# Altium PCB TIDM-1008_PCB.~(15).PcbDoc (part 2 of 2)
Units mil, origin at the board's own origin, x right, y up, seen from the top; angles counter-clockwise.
Board outline 2200 x 2300 mil, 4 copper layers (Top Layer, Power Layer, Ground Plane, Bottom Layer), stack 79.834 mil thick; 196 components, 111 nets, 520 pads, 167 vias.
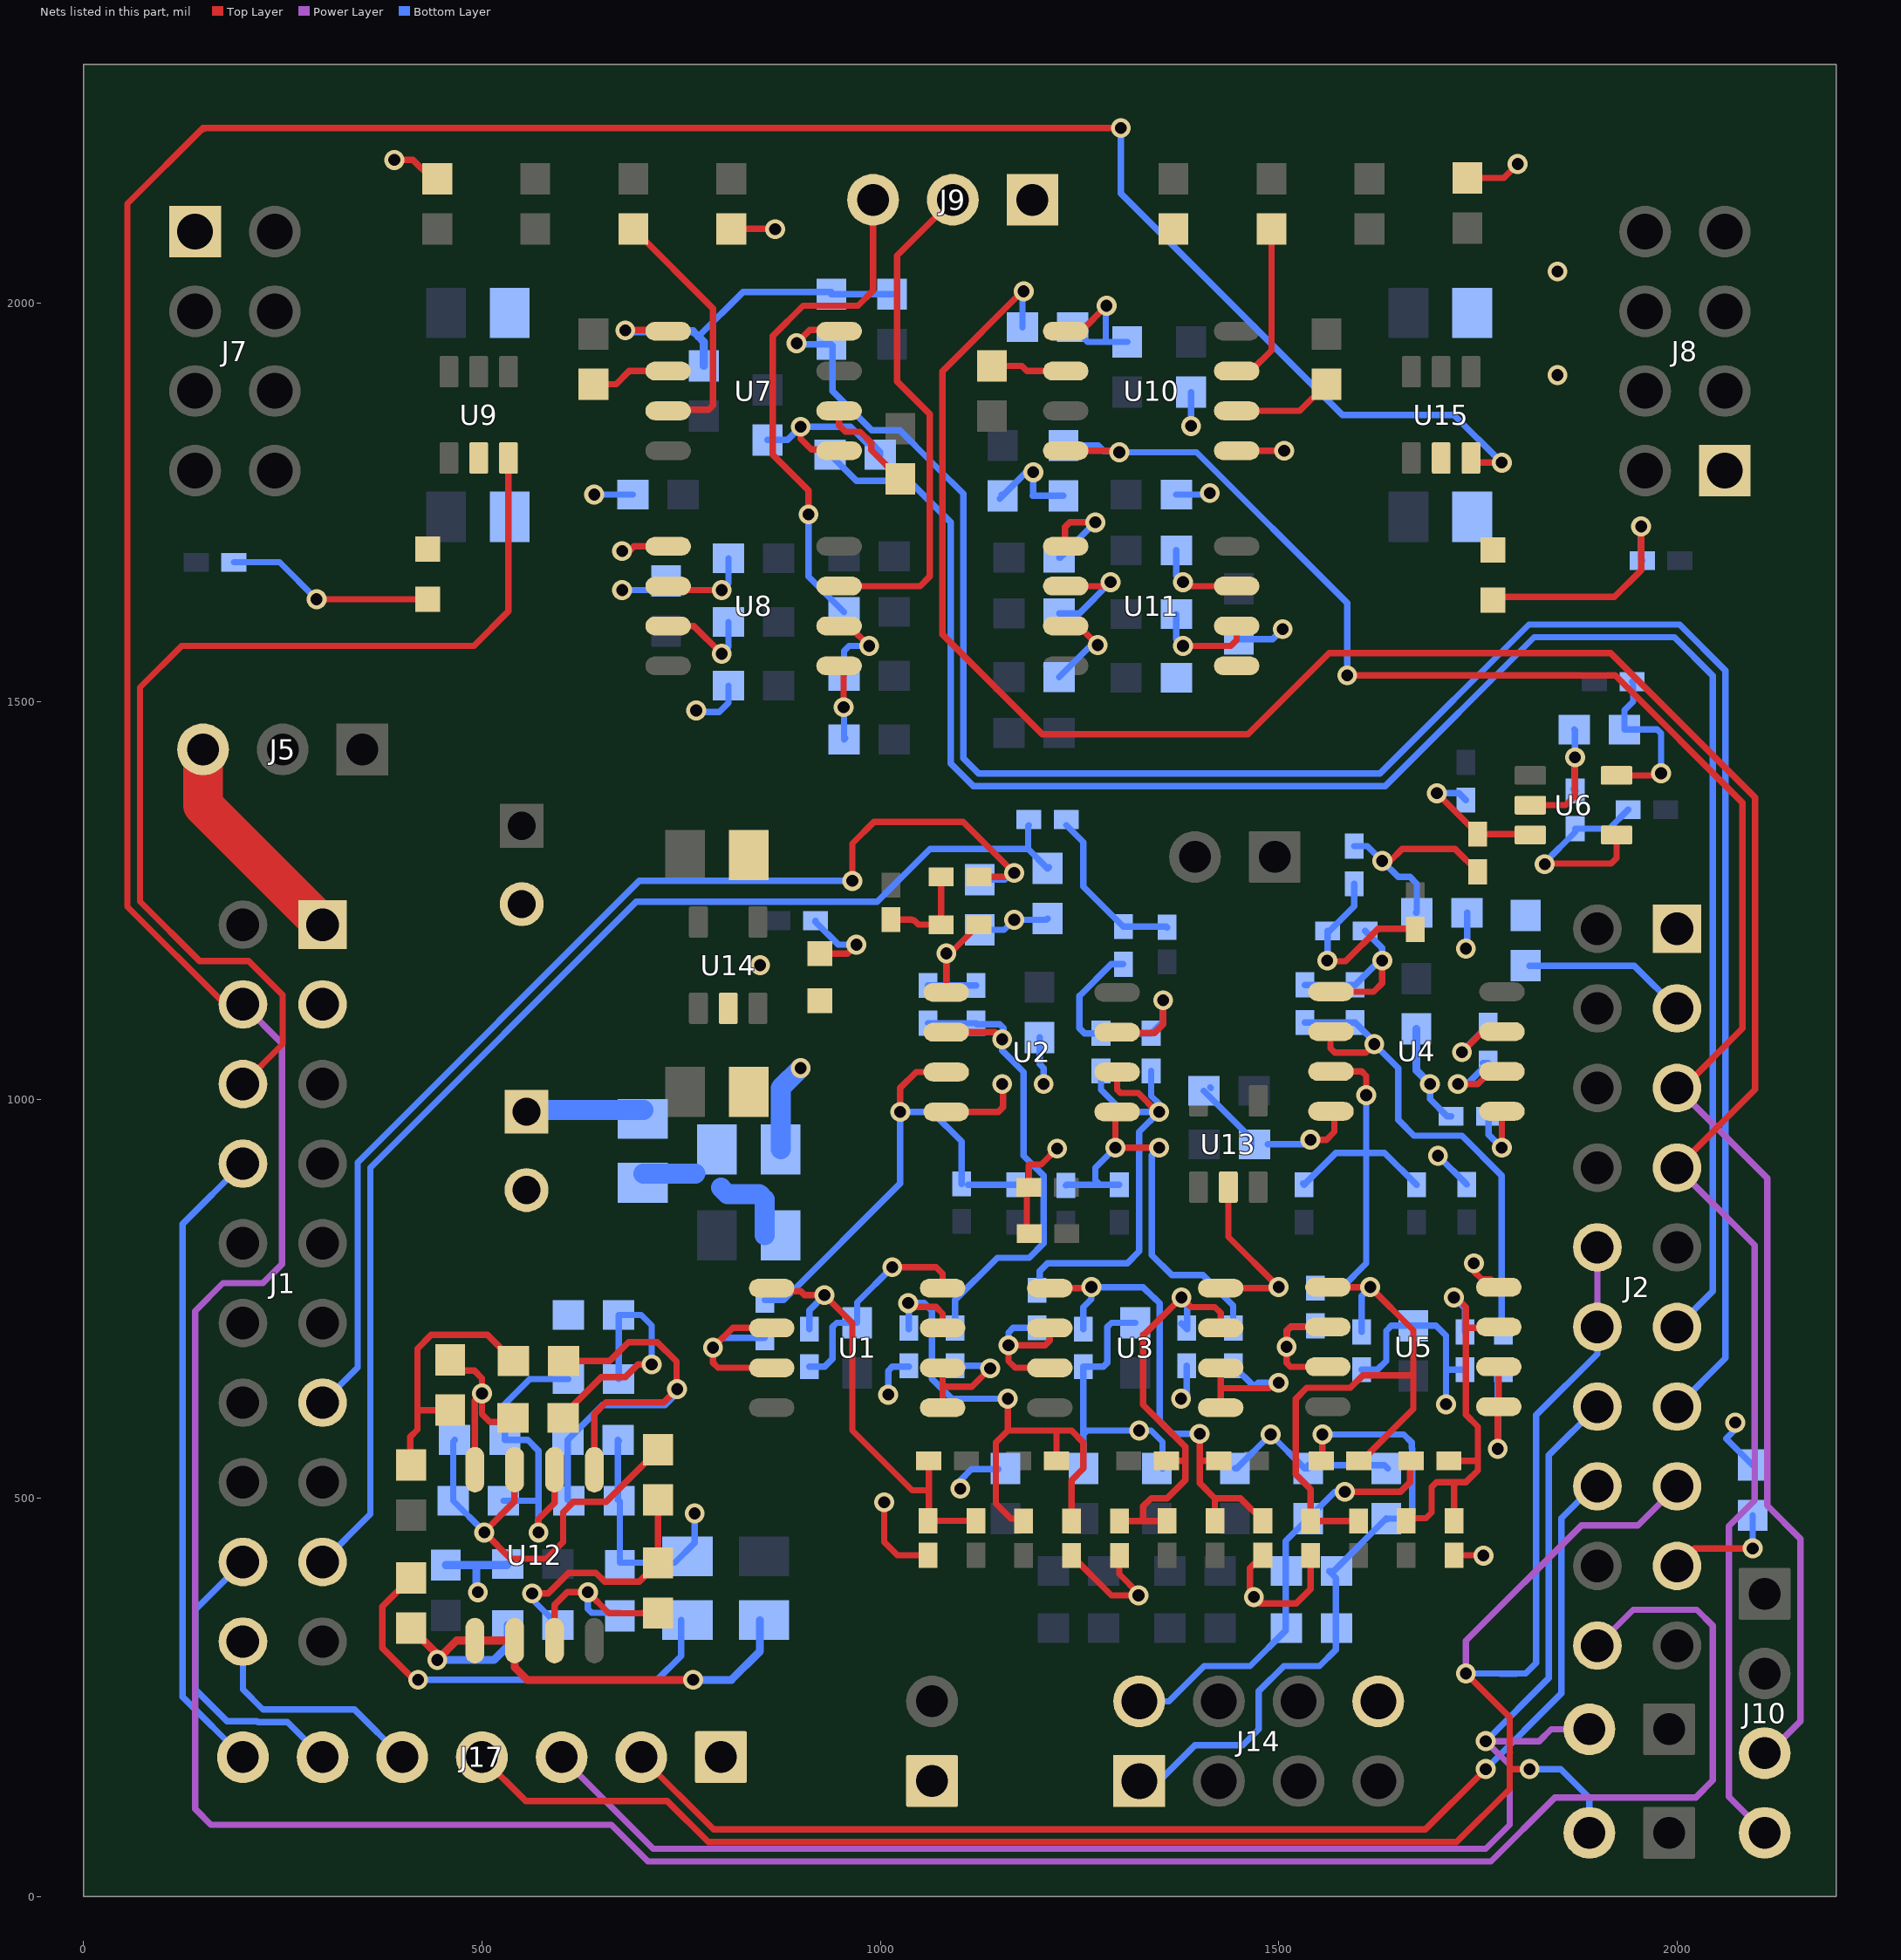
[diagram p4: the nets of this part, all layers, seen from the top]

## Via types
v1: diameter 25, hole 15, Top Layer to Bottom Layer, 167 vias

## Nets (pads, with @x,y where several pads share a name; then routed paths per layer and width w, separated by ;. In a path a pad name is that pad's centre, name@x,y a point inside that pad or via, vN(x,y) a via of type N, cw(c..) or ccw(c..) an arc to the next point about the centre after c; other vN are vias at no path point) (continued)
GND: C2.1 C3.1 C4.1 C5.2 C7.2 C8.2 C9.2 C10.2 C13.1 C14.1 C15.2 C17.2 C18.2 C19.2 C20.2 C23.1 C24.1 C25.1 C26.1 C27.2 C28.2 C30.2 C31.2 C32.2 C33.2 C35.1 C36.1 C37.2 C38.1 C39.1 C40.2 C41.1 C42.1 C43.2 C44.1 C45.1 C46.2 C49.2 C51.1 C52.2 C53.2 C54.1 C55.2 C56.1 C57.2 C58.1 C59.1 C60.2 C61.2 C62.2 C63.2 C64.2 C65.2 D2.2 D4.2 D7.2 D9.2 D12.2 D14.2 D16.1 D17.1 D18.2 J1.3 J2.1 J6.2 J7.1 J8.1 J9.1 J14.8 J15.1 J16.2 J17.1 R20.1 R40.2 R41.1 R56.2 R57.1 R64.1 R72.1 R73.1 R74.1 U1.4 U2.4 U3.4 U4.4 U5.4 U6.2 U7.5 U8.5 U9.2 U10.5 U11.5 U12.8 U13.2 U14.2 U15.2 | length 5177.7
  Top Layer w8: v1(390,2180) 413.5,2180 435.5,2158 C37.2@440,2162.5 ; C51.1@459.83,660.21 490.47,660.21 500.12,650.57 v1(500.12,631.57) ; U12.8@491.12,535.86 491.12,622.57 v1(500.12,631.57) ; C49.2@537.56,596 509.69,596 500.12,605.57 v1(500.12,631.57) ; v1(676,1689) 685,1689 691,1695 U8.5@733.72,1695 ; v1(680,1966) 686,1966 686.5,1966.5 U7.5@733.79,1966.5 ; C36.1@813,2093.5 v1@867.5,2093.5 ; v1(1005,495) 1005,445 1021.66,428.34 D4.2@1059.97,428.34 ; v1(1015,790) 1070,790 1078.25,781.75 U1.4@1078.25,763.73 ; U2.4@1082.72,985 1148,985 1154,991 1154,1019 v1(1153,1020) ; C10.2@1186.89,831.99 1184,834.88 1184,887.62 C20.2@1186.38,890 1186.38,918.38 1187,919 1202,919 v1(1222,939) ; D2.2@1240.03,428.03 1290.06,378 v1(1324,378) 1324,380.85 1300.09,404.76 D9.2@1300.09,428.04 ; U3.4@1427.28,763.73 1498.73,763.73 v1(1500,765) 1436.85,828.15 U13.2@1436.85,890.54 ; U10.5@1447.28,1815 v1(1507,1815) ; D7.2@1480.14,428.34 1464,412.19 1464,380 1468,376 v1(1469,376) 1469,375 1476,368 1522,368 1540,386 1540,427.88 D14.2@1540.16,428.04 ; v1(1540,950) 1560,950 1570,960 1570,981.45 U4.4@1565.69,985.76 ; D12.2@1720,428.16 D12.2@1720.2,428.36 1756.64,428.36 v1(1757,428) ; C43.2@1737,2157.5 1782.5,2157.5 v1(1800,2175) ; v1(1745,795) 1745,785 1755,775 1766.31,775 U5.4@1776.31,765 ; U6.2@1815.87,1370.01 1860.01,1370.01 1872,1382 v1(1872,1430) ; J2.1@2000,1201.5 J2.1@2000,1214.98
  Bottom Layer w8: C57.2@454.64,416.07 C57.2@455.15,416.57 ; v1(641,1760) C40.2@689.5,1760 ; R72.1@671.93,572 R72.1@670.79,573.14 670.79,498.29 C53.2@672.31,496.77 673.08,496 673.08,419.05 742.05,419.05 767,444 v1(767,481) ; v1(676,1640) 719.5,1640 C38.1@731,1651.5 ; v1(769,1489) 771,1487 798,1487 809.5,1498.5 C39.1@809.5,1520 ; 771.75,1958.25 827.88,2014.37 938.5,2014.37 R41.1@938.5,2011.5 R40.2@1014.87,2011.5 ; C9.2@910.97,665.11 930.11,665.11 940,675 940,715 945.22,720.22 C2.1@970.97,720.22 970.97,745.97 v1(1015,790) ; v1(1010,630) 1010,660 1015.11,665.11 C5.2@1035.97,665.11 ; v1(1100.36,512) 1100.36,522.36 1114.5,536.5 C3.1@1148,536.5 ; C7.2@1124.78,1213.5 1155.5,1213.5 v1(1168,1226) 1208.5,1226 C17.2@1210,1227.5 ; R56.2@1150,1754.87 R56.2@1153.63,1758.5 ; R56.2@1152.13,1760 R56.2@1153.63,1758.5 ; C4.1@1200,1078.5 1200,1045 1205,1040 v1(1205,1020) ; R57.1@1230,1758.5 1191.5,1758.5 1192,1759.01 v1(1192,1788) 1183.13,1788 R56.2@1153.63,1758.5 ; C8.2@1255,537.3 1255,580 ; C13.1@1320,720.22 1290.22,720.22 1285,715 1285,670 1280.11,665.11 C15.2@1255,665.11 1255,580 ; C18.2@1354.24,537.23 1354.24,570.76 1340,585 v1(1325,585) 1260,585 1255,580 ; C45.1@1371.5,1760 1411.71,1760 v1(1413.62,1761.91) v1@1417.15,1765.45 ; v1(1377.5,625) 1380,625 1385,630 1384.71,630.29 C19.2@1384.71,666.38 ; v1(1390,1846) C41.1@1390,1888.5 ; C58.1@1406,1011.54 1466,951.54 1466,940.11 C59.1@1465.89,940 ; C58.1@1414.2,1015.86 C58.1@1415,1015.06 ; C14.1@1445,537.5 1447.5,537.5 v1(1490,580) 1532.5,537.5 C25.1@1537,537.5 ; C44.1@1450,1578.5 1492.5,1578.5 v1(1505,1591) ; C59.1@1486.5,944.32 1534.32,944.32 v1(1540,950) ; v1@1507,1813 v1(1507,1815) ; C25.1@1537,541.5 1632.8,541.5 C31.2@1637,537.3 ; C32.2@1604.03,661.38 1623.93,661.38 1635,672.45 1635,710 1641.5,716.5 C23.1@1669.03,716.5 1697.5,716.5 1710,704 1710,663 ; v1(1690,1020) 1690,1001 1711.47,979.53 R20.1@1716.38,979.53 ; v1(1700,930) 1700,929.88 C33.2@1736,893.88 ; v1(1710,618) 1710,663 ; C28.2@1732.36,660 C28.2@1733.74,661.38 1711.62,661.38 1710,663 ; v1(1735,1190) 1736.5,1191.5 C30.2@1736.5,1235 ; C24.1@1871.07,1465 1872,1464.07 v1(1872,1430) 1872,1392.01 1870,1390.01 C27.2@1872.18,1387.82 C27.2@1872.36,1388 ; v1(2073,595) 2073,586.5 2061.5,575 R73.1@2095,541.5
  Bottom Layer w10: C57.2@454.64,416.07 492.9,416.07 ; v1(495,382) 492.9,384.1 492.9,416.07 ; C52.2@532.36,417.27 531.16,416.07 492.9,416.07 ; v1(680,1966) 681,1965 765,1965 771.75,1958.25 778.5,1951.5 C35.1@778.5,1921.5 ; C26.1@1672.97,1089.27 1672.97,1037.03 v1(1690,1020)
  Bottom Layer w25: C56.1@875,938 875,1015 v1(900,1040)
  other v1: 849.1,1169.14 1850,1910 1850,2040 868,2093
I+: C29.2 C31.1 J14.1 R26.1 R30.1 | length 822.3
  Top Layer w8: R30.1@1553.37,547.02 1555,548.66 1555,570 1560,575 v1(1555,580)
  Bottom Layer w8: J14.1@1325,145 1350,145 1395,190 1455,190 1475,210 1475,257.73 1506.63,289.35 1551.35,289.35 1572,310 1572,400.01 1563.47,408.54 1569.04,408.54 C31.1@1635,474.5 ; v1(1555,580) 1657,580 1667,570 1667,563.05 1667.57,562.47 1667.57,480.57 1661.3,474.3 1637,474.3 C31.1@1636.1,473.4
I-: C25.2 C29.1 J14.2 R24.1 R26.2 | length 547.4
  Top Layer w8: v1(1583,508) 1653,508 1665,520 1665,545.65 R24.1@1666.38,547.02
  Bottom Layer w8: J14.2@1325,245 1362.27,245 1406.63,289.35 1464.35,289.35 1509,334 1509,446.5 C25.2@1537,474.5 1570.5,508 v1(1583,508)
Launchpad-5V: J1.1 J5.3 | length 283.5
  Top Layer w50: J5.3@150,1440 150,1370 J1.1@300,1220
  Bottom Layer w25: J1.1@300,1220 J1.1@301,1219
NetC1_1: C1.1 R1.2 R5.1 U2.1 | length 205.1
  Top Layer w8: U2.1@1082.72,1135 1082.72,1183.72 v1(1083,1184) 1087.62,1184 R5.1@1123.62,1220
  Bottom Layer w8: C1.1@1060,1143.62 1082.72,1143.62 ; v1(1083,1184) 1083,1143.9 1082.72,1143.62 ; R1.2@1120,1143.62 1082.72,1143.62
NetC1_2: C1.2 R1.1 R3.2 U2.2 | length 640.8
  Top Layer w8: U2.2@1082,1084.28 U2.2@1082.72,1085 1144,1085 v1(1153,1076)
  Bottom Layer w8: C1.2@1060,1096.38 R1.1@1120,1096.38 1121.38,1095 1150,1095 1155,1090 1155,1078 v1(1153,1076) 1153,1062 1180,1035 1180,930 1205,905 1205,820 1186.89,801.89 1146.89,801.89 1093.98,748.98 R3.2@1093.98,713.62
NetC5_1: C5.1 D1.2 D2.1 R2.2 U1.3 | length 750.1
  Top Layer w8: v1(1035,745) 1039.96,740.04 1069.96,740.04 1078.25,731.75 U1.3@1078.25,713.73 ; v1(1160,625) 1160,585 ; D1.2@1180,471.34 1177.03,474.3 1164,474.3 1145,493.3 1145,570 1160,585 ; R2.2@1221.12,547.01 1221.12,584.88 1221,585 ; D2.1@1240.03,471.34 1240.03,522.33 1255,537.3 1255,570 1240,585 1221,585 ; 1160,585 1221,585
  Bottom Layer w8: v1(1035,745) v1@1035.97,745 ; C5.1@1035.97,712.35 v1@1035.97,745 ; v1(1160,625) 1090,625 1065,650 1065,735.04 1055.04,745 v1@1035.97,745
NetC9_1: C9.1 D4.1 D5.2 R7.2 U1.5 | length 570.8
  Top Layer w8: U1.5@862.41,765 U1.5@863.69,763.73 867.41,760 900,760 905,755 v1(930,755) 965,720 965,585 1040.03,509.97 1060.67,509.97 1060.87,509.77 ; R7.2@1059.97,546.11 R7.2@1060.87,547 1060.87,509.77 ; D5.2@1119.99,471.64 D4.1@1059.97,471.64 1060.87,472.54 1060.87,509.77
  Bottom Layer w8: C9.1@910.97,712.35 910.97,735.97 v1(930,755)
NetC11_2: C11.2 R8.2 R9.1 U2.3 | length 622.3
  Top Layer w8: v1(1025,985) 1025,1015 1045,1035 U2.3@1082.72,1035
  Bottom Layer w8: R8.2@855,748.62 878.62,748.62 1025,895 v1(1025,985) 1065,985 1102,948 C11.2@1102,894.62 ; C11.2@1110,893.62 R9.1@1170,893.62
NetC12_1: C12.1 R10.2 R14.1 U2.7 | length 345
  Top Layer w8: U2.7@1297.29,1085 1298.29,1084 1344,1084 1355,1095 v1(1355,1125)
  Bottom Layer w8: R14.1@1305,1170.38 1289.85,1170.38 1250.1,1130.63 1250,1130.63 1250,1090 1256.38,1083.62 R10.2@1277.03,1083.62 C12.1@1340,1083.62 1355,1098.62 v1(1355,1125)
NetC12_2: C12.2 R10.1 R12.2 U2.6 | length 595.8
  Top Layer w8: U2.6@1297.29,1035 1297.29,1012.71 1301.32,1008.68 1323.83,1008.68 1347.51,985 v1(1350,985)
  Bottom Layer w8: R12.2@1196.99,761.08 1200,764.09 1200,785 1210,795 1310,795 1325,810 1325,960 v1(1350,985) ; R10.1@1277.03,1036.38 1277.03,1012.97 1305,985 v1(1350,985) ; C12.2@1340,1036.38 1340,1005 1350,995 v1(1350,985)
NetC15_1: C15.1 D6.2 D7.1 R11.2 U3.5 | length 622.3
  Top Layer w8: U3.5@1212.72,763.73 1263.73,763.73 v1(1265,765) ; v1(1400.87,580.87) 1400.87,545 ; D6.2@1420.11,471.65 1420,471.76 1420,500 ; R11.2@1424.9,547.01 1402.88,547.01 1400.87,545 ; D7.1@1480.14,471.65 1451.79,500 1420,500 ; 1400.87,545 1400.87,519.13 1420,500
  Bottom Layer w8: C15.1@1255,712.35 1255,740 1265,750 v1(1265,765) 1330,765 1343.22,751.78 1343.62,751.78 1350.57,744.83 1350.57,596.87 1366.58,580.87 v1(1400.87,580.87)
NetC19_1: C19.1 D9.1 D10.2 R16.2 U3.3 | length 569.4
  Top Layer w8: D9.1@1300.09,471.35 1330,471.35 ; R16.2@1359.13,547.01 1382.99,547.01 ; D10.2@1360.1,471.65 1359.79,471.35 1330,471.35 ; U3.3@1427.28,713.73 1427.28,732.72 1420,740 1390,740 v1(1378,752) 1331,705 1330,705 1330,617.28 1382.99,564.29 1382.99,547.01 ; 1330,471.35 1330,490 1340,500 1360,500 1382.99,522.99 1382.99,547.01
  Bottom Layer w8: C19.1@1378,719.35 1385,712.35 1385,745 v1(1378,752)
NetC21_2: C21.2 R18.2 R19.1 U2.5 | length 544.5
  Top Layer w8: U2.5@1297.29,985 1295,982.71 v1(1295,940) v1(1350,940)
  Bottom Layer w8: R19.1@1232.97,892.62 1233.97,893.62 1276,893.62 ; v1(1295,940) 1270,915 1270,899.62 1276,893.62 ; v1(1350,940) 1340.87,930.87 1340.87,805 1365.87,780 1405,780 1443.01,741.99 R18.2@1443.01,716.08 ; 1276,893.62 C21.2@1300,893.62 1276,893.62
NetC22_1: C22.1 R22.2 R27.1 U4.1 | length 252.8
  Top Layer w8: U4.1@1565.69,1135.76 1619.24,1135.76 1630,1146.52 v1(1630,1175)
  Bottom Layer w8: C22.1@1532.97,1144.38 R22.2@1595.94,1144.38 1626.56,1175 v1(1630,1175) 1630,1190.65 R27.1@1608.66,1211.99
NetC22_2: C22.2 R22.1 R25.2 U4.2 | length 633.8
  Top Layer w8: U4.2@1565.69,1085.76 1565,1085.07 1565,1065 1570.55,1059.45 1609.45,1059.45 v1(1620,1070)
  Bottom Layer w8: C22.2@1532.97,1097.14 R22.1@1595.94,1097.14 1620,1073.08 v1(1620,1070) 1650,1040 1650,975 1670,955 1730,955 1780,905 R25.2@1780,720.37
NetC24_2: C24.2 R21.1 U6.5 | length 216.4
  Top Layer w8: U6.5@1924.13,1407.41 v1@1977.41,1407.41
  Bottom Layer w8: R21.1@1943.62,1525 1945,1523.62 1945,1500 1934.07,1489.07 C24.2@1934.07,1465 1975,1465 1980,1460 v1(1980,1410)
NetC27_1: C27.1 R23.2 U6.4 | length 258.9
  Top Layer w8: v1(1834,1296) 1834.75,1296.75 1917.3,1296.75 1924.13,1303.58 U6.4@1924.13,1332.6
  Bottom Layer w8: v1(1834,1296) 1834,1298 1872.18,1336.18 C27.1@1872.18,1340.58 1914.94,1340.58 R23.2@1938.56,1364.2
NetC28_1: C28.1 D11.2 D12.1 R24.2 U5.3 | length 543.1
  Top Layer w8: D11.2@1660.19,471.65 1663.53,475 1685,475 1692,482 1692,514 1698,520 1720,520 ; R24.2@1713.62,547.02 1747.02,547.02 1750,550 ; v1(1720,752) 1723,752 1735,740 1735,714 ; D12.1@1720.2,471.67 1720.2,519.8 1720,520 ; U5.3@1776.31,715 1775.31,714 1735,714 ; 1720,520 1735,520 1750,535 1750,550 ; 1735,714 1735,605 1750,590 1750,550
  Bottom Layer w8: v1(1720,752) 1733.26,738.74 1733.74,738.74 C28.1@1733.74,708.62
NetC30_1: C30.1 R28.2 R29.1 | length 273.6
  Top Layer w8: v1(1630,1300) 1640,1300 1655,1315 1721.38,1315 R29.1@1750,1286.38
  Bottom Layer w8: R28.2@1595,1318.62 1611.38,1318.62 v1(1630,1300) 1650,1280 1665,1280 1673.5,1271.5 C30.1@1673.5,1235 C30.1@1672.53,1235
NetC32_1: C32.1 D14.1 D15.2 R30.2 U5.5 | length 766.5
  Top Layer w8: U5.5@1561.75,765 v1(1615,765) 1669.03,710.97 1669.03,653.5 ; D15.2@1600.18,471.34 D14.1@1540.16,471.34 1540.16,511.17 1521.33,530 1521.33,624.81 1535.2,638.68 1589.94,638.68 1605.63,654.37 1668.16,654.37 1669.03,653.5 ; R30.2@1600.61,547.02 1604.02,547.02 1669,612 1669,634 ; 1669.03,634.03 1669.03,653.5
  Bottom Layer w8: C32.1@1604.03,708.62 1604.03,754.03 v1(1615,765)
NetC34_2: C34.2 R32.2 R33.1 U4.3 | length 534.9
  Top Layer w8: U4.3@1565.69,1035.76 1604.24,1035.76 1610,1030 v1(1610,1006)
  Bottom Layer w8: C34.2@1530.5,895 C34.2@1531.88,893.62 1571.88,933.62 1610,933.62 ; R32.2@1546.02,763.62 1547.4,765 1580,765 1610,795 1610,933.62 ; v1(1610,1006) 1610,933.62 ; R33.1@1672.97,893.62 1632.97,933.62 1610,933.62
NetC47_1: C47.1 R66.2 R67.1 U12.7 | length 538.8
  Top Layer w8: U12.7@541.66,535.31 U12.7@541.12,535.86 541,535.74 541,496 503,458 v1(503,457) 536,424 581,424 602,445 602,482.46 614.98,495.44 655.76,495.44 R67.1@721.08,560.76
  Bottom Layer w8: R66.2@465.86,573.14 464.07,571.35 C47.1@464.07,496.77 503,457.85 v1(503,457)
NetC47_2: C47.2 R65.2 R66.1 U12.6 | length 417.3
  Top Layer w8: v1(571,457) 571,473.91 591.12,494.02 U12.6@591.12,535.86
  Bottom Layer w8: C47.2@527.06,496.77 568.92,496.77 ; v1(571,457) 571,559.69 557.55,573.14 R66.1@528.85,573.14 528.85,618.31 560.12,649.58 R65.2@608.62,649.58
NetC48_1: C48.1 C50.2 R71.2 U12.1 U12.2 | length 691.4
  Top Layer w10: R71.2@411.09,337.04 444,304.13 v1(444,297) 468.29,321.29 U12.1@491.12,321.29 U12.2@541.12,321.29 541.12,287.88 557,272 v1(765,272)
  Bottom Layer w10: v1@440,302 444,298 v1(444,297) 515,297 532.36,314.36 C48.1@532.36,340.9 ; v1(765,272) 813,272 849,308 C50.2@849,347
NetC48_2: C48.2 R67.2 R68.1 | length 316.7
  Top Layer w8: v1(563.12,380.57) 583.12,380.57 608.92,406.37 643.1,406.37 654.33,395.14 697.39,395.14 R68.1@721.08,418.82 R67.2@721.08,497.77
  Bottom Layer w8: v1@563.92,379.77 v1(563.12,380.57) 563.12,373.14 C48.2@595.36,340.9 C48.2@595.03,340.57
NetC49_1: C49.1 R64.2 R65.1 | length 317.1
  Top Layer w8: C49.1@601.75,600.96 601.75,603.75 650,652 680,652 696,668 v1(713,668)
  Bottom Layer w8: R65.1@671.5,649.7 R65.1@671.61,649.58 671.61,729.88 R64.2@671.5,730 699.95,730 713,716.95 v1(713,668)
NetC51_2: C51.2 R69.2 R70.1 | length 333.7
  Top Layer w8: R69.2@411.15,541.97 410,543.12 410,577 419.12,586.12 419.12,612 ; C51.2@459.18,596.57 C51.2@459.83,597.22 ; C51.2@460,610.5 420.61,610.5 419.12,612 ; R70.1@539.62,672.37 507,704.99 507,705.06 436.38,705.06 419.12,687.79 419.12,612
NetC53_1: C53.1 R70.2 R72.2 U12.5 | length 628.9
  Top Layer w8: R70.2@604.15,673.91 R70.2@602.61,672.37 660.37,672.37 684,696 720,696 744.37,671.63 744.37,637.63 v1(745,637) 728.13,620.13 655.67,620.13 641.12,605.57 U12.5@641.12,535.86
  Bottom Layer w8: C53.1@609.31,496.77 607.8,498.29 R72.2@607.8,573.14 651.65,617 730,617 745,632 v1(745,637)
NetC54_2: C54.2 R68.2 U12.3 | length 235.5
  Top Layer w8: U12.3@591.12,321.29 591.12,366.12 607,382 v1(633,382) 659.43,355.57 700.82,355.57 701.08,355.83
  Bottom Layer w8: v1(633,382) 633,361 637.94,356.06 C54.2@673.08,356.06
NetC55_1: C55.1 R71.1 | length 552
  Top Layer w8: R71.1@411.09,400.03 375,363.94 375,312 415,272 v1(420,272)
  Bottom Layer w8: v1(420,272) 720,272 750,302 C55.1@750,347
NetC56_2: C56.2 L1.2 L2.1 | length 176.6
  Bottom Layer w25: L1.2@702.57,907.32 767.68,907.32 ; 800,890 808.13,881.87 848.13,881.87 855,875 855,830 L2.1@855,835.31
NetD3_2: D3.2 R5.2 R6.1 | length 125.5
  Top Layer w8: D3.2@1013.49,1226.35 1039.18,1226.35 1039.9,1225.63 1042.37,1225.63 1048,1220 R5.2@1076.38,1220 R6.1@1076.38,1280
NetD8_2: D8.2 R14.2 R15.1 | length 212.3
  Bottom Layer w8: R15.1@1233.62,1345 1255,1323.62 1255,1267.62 R14.2@1305,1217.62 1359.03,1217.62 D8.2@1360,1216.65
NetD13_2: D13.2 R27.2 R28.1 | length 240.8
  Top Layer w8: v1@1561,1174 1584,1174 1625,1215 1670.62,1215 D13.2@1671.51,1214.11
  Bottom Layer w8: v1@1561,1174 1561,1181 1561.41,1181.41 R27.2@1561.41,1211.99 1563.99,1211.99 1595,1243 R28.1@1595,1271.38
  other v1: 1561,1175
NetD16_2: D16.2 R48.1 | length 262.6
  Top Layer w8: v1(292.5,1628.5) D16.2@432,1628.5
  Bottom Layer w8: R48.1@188.62,1675 246,1675 v1(292.5,1628.5)
NetD17_2: D17.2 R54.1 | length 299.6
  Top Layer w8: D17.2@1768.02,1631.47 1921.47,1631.47 1955,1665 v1(1955,1720)
  Bottom Layer w8: v1(1955,1720) 1955,1678.22 R54.1@1956.38,1676.84
NetD18_1: D18.1 R78.1 | length 117.2
  Top Layer w8: D18.1@925.43,1185 D18.1@924.1,1183.66 958.66,1183.66 v1(970,1195)
  Bottom Layer w8: R78.1@918.62,1225 918.62,1223.38 947,1195 v1(970,1195)
NetJ9_2: J9.2 U8.3 | length 646.1
  Top Layer w8: U8.3@948.28,1645 1050,1645 1062.13,1657.13 1062.13,1861 1021,1902.13 1021,2060 J9.2@1091,2130 ; J9.2@1074.13,2124.13 J9.2@1080,2130
NetJ9_3: J9.3 R45.1 | length 647.2
  Top Layer w8: v1(910,1735) 910,1765 865,1810 865,1959 903,1997 972,1997 991,2016 J9.3@991,2130
  Bottom Layer w8: v1(910,1735) 910,1657 R45.1@954.5,1612.5
NetJ16_1: J16.1 L1.1 | length 147.4
  Bottom Layer w25: J16.1@556,985.21 558.1,987.32 L1.1@702.57,987.32
NetR3_1: R3.1 U1.1 U1.2 | length 166.6
  Top Layer w8: U1.1@1078.25,613.73 1078.25,640 ; U1.2@1078.25,663.73 1078.25,640 ; v1(1138,663) 1115,640 1078.25,640
  Bottom Layer w8: R3.1@1095.36,665 R3.1@1093.98,666.38 1134.62,666.38 v1(1138,663)
NetR8_1: R8.1 U1.6 U1.7 | length 251.4
  Top Layer w8: U1.7@862.41,665 U1.7@863.69,663.73 796.27,663.73 790,670 v1(790,689) 815,714 863.41,714 U1.6@863.69,713.73
  Bottom Layer w8: v1(790,689) 802.38,701.38 R8.1@855,701.38
NetR12_1: R12.1 U3.6 U3.7 | length 212
  Top Layer w8: U3.6@1212,713.01 U3.6@1212.72,713.73 1212.72,697.72 1207,692 v1(1161,692) 1161,672 1169.27,663.73 U3.7@1212.72,663.73
  Bottom Layer w8: v1@1169,694 1164,689 v1(1161,692) 1161,708 1166.83,713.83 R12.1@1196.99,713.83
NetR17_1: R17.1 U4.7 | length 108.2
  Top Layer w8: v1(1730,1060) 1755.76,1085.76 U4.7@1780.25,1085.76
  Bottom Layer w8: v1(1730,1060) 1730,1060.65 R17.1@1762.97,1093.62
NetR17_2: R17.2 U4.6 | length 117.3
  Top Layer w8: v1(1725,1020) 1750,1020 1765.76,1035.76 U4.6@1780.25,1035.76
  Bottom Layer w8: v1(1725,1020) 1736.59,1020 R17.2@1762.97,1046.38 R17.2@1756.38,1046.38
NetR18_1: R18.1 U3.1 U3.2 | length 195.6
  Top Layer w8: U3.1@1427.28,613.73 1427.28,638.09 ; U3.2@1427.28,663.73 1427.28,638.09 ; v1(1500,645) 1495,645 1488.09,638.09 1427.28,638.09
  Bottom Layer w8: R18.1@1443.01,666.38 1469.39,640 1474.39,645 v1(1500,645)
NetR20_2: R20.2 U4.5 | length 82.2
  Top Layer w8: v1@1780,950 1780.25,950.25 U4.5@1780.25,985.76
  Bottom Layer w8: R20.2@1763.62,979.53 1763.62,956.38 v1(1780,940)
NetR25_1: R25.1 U5.1 U5.2 | length 205.8
  Top Layer w8: v1(1775,562) 1775,613.69 U5.1@1776.31,615 U5.2@1776.31,665
  Bottom Layer w8: v1(1775,562) 1775,654.38 R25.1@1782,661.38
NetR29_2: R29.2 R31.1 U6.3 | length 178.9
  Top Layer w8: v1(1698.62,1385) R29.2@1750,1333.62 1814.85,1333.62 U6.3@1815.87,1332.6
  Bottom Layer w8: v1(1698.62,1385) 1726.38,1385 R31.1@1735,1376.38
NetR32_1: R32.1 U5.6 U5.7 | length 206.3
  Top Layer w8: U5.7@1561.75,665 1515,665 1510,670 v1(1510,690) 1510,710 1515,715 U5.6@1561.75,715
  Bottom Layer w8: v1(1510,690) 1510,710 1515,715 1544.64,715 R32.1@1546.02,716.38
NetR34_1: R34.1 U7.7 | length 321.4
  Top Layer w8: R34.1@690,2093.5 790,1993.5 790,1872 784.5,1866.5 U7.7@733.79,1866.5
NetR35_1: R35.1 R36.2 U7.1 | length 233.9
  Top Layer w8: v1(900,1845) 900,1830 913.5,1816.5 U7.1@948.36,1816.5
  Bottom Layer w8: R35.1@858.5,1828.5 883.5,1828.5 v1(900,1845) 962.55,1845 982.85,1824.7 988.85,1824.7 1000,1813.55 R36.2@1000,1810
NetR37_1: R37.1 U7.2 | length 129.5
  Top Layer w8: U7.2@948.36,1866.5 948.36,1846.82 956.5,1838.68 974.83,1838.68 988.7,1824.81 988.7,1815.8 R37.1@1025,1779.5
NetR39_1: R39.1 U7.6 | length 105.5
  Top Layer w8: R39.1@640,1898.5 668.5,1898.5 685,1915 U7.6@733.72,1915 U7.6@730.21,1918.5
NetR42_1: R42.1 U8.7 | length 125.3
  Top Layer w8: U8.7@733.72,1595 766,1595 v1(801,1560)
  Bottom Layer w8: v1(801,1560) 809.5,1568.5 R42.1@809.5,1600
NetR43_1: R43.1 U8.1 | length 109.6
  Top Layer w8: U8.1@951,1542.28 U8.1@948.28,1545 950,1543.28 954,1539.28 v1(954,1493) v1@954,1499.43
  Bottom Layer w8: v1(954,1493) 954,1486 954.5,1485.5 R43.1@954.5,1455.49 ; R43.1@954.5,1455.49 R43.1@954.5,1452.5 956,1454 R43.1@954.5,1455.49
NetR44_1: R44.1 U8.2 | length 113.3
  Top Layer w8: U8.2@948.28,1595 961,1595 v1(986,1570)
  Bottom Layer w8: R44.1@954.5,1532.5 954.5,1563.5 961,1570 v1(986,1570)
NetR47_1: R47.1 U8.6 | length 112.9
  Top Layer w8: U8.6@733.72,1645 738.72,1640 v1(801,1640)
  Bottom Layer w8: v1(801,1640) 809.5,1648.5 R47.1@809.5,1680
NetR49_1: R49.1 U10.7 | length 207
  Top Layer w8: U10.7@1447.28,1915 1465,1915 1491,1941 R49.1@1491,2093.5
NetR50_1: R50.1 R51.2 U10.1 | length 186.6
  Top Layer w8: U10.1@1232.72,1965 1252,1965 v1(1284,1997)
  Bottom Layer w8: R51.2@1241.5,1970 1260,1951.5 1283,1951.5 ; v1(1284,1997) 1284,1987 1283,1986 1283,1951.5 ; R50.1@1310,1951.5 1283,1951.5
NetR52_1: R52.1 U10.2 | length 104.6
  Top Layer w8: R52.1@1140,1921.5 1177.5,1921.5 1184,1915 U10.2@1232.72,1915 U10.2@1226.22,1921.5
NetR55_1: R55.1 U10.6 | length 126.6
  Top Layer w8: U10.6@1447.28,1865 1526.5,1865 R55.1@1560,1898.5
NetR58_1: R58.1 U11.7 | length 112.9
  Top Layer w8: v1(1380,1650) 1385,1645 U11.7@1447.28,1645
  Bottom Layer w8: R58.1@1371.5,1690 1371.5,1658.5 v1(1380,1650)
NetR59_1: R59.1 U11.1 | length 135.9
  Top Layer w8: U11.1@1240,1695 U11.1@1232.72,1695 1232,1695.72 1232,1719 1238,1725 v1(1270,1725)
  Bottom Layer w8: R59.1@1224.5,1680.78 1225.78,1680.78 v1(1270,1725)
NetR60_1: R60.1 U11.2 | length 139.1
  Top Layer w8: U11.2@1232.72,1645 1284,1645 v1(1289,1650)
  Bottom Layer w8: R60.1@1224.5,1610.78 1249.78,1610.78 v1(1289,1650)
NetR61_1: R61.1 U11.3 | length 115.4
  Top Layer w8: U11.3@1232.72,1595 1249,1595 v1(1273,1571)
  Bottom Layer w8: R61.1@1224.5,1530.78 1264.71,1571 v1(1273,1571)
NetR63_1: R63.1 U11.6 | length 131.5
  Top Layer w8: v1(1380,1570) 1440,1570 1447.28,1577.28 U11.6@1447.28,1595
  Bottom Layer w8: R63.1@1371.5,1610 1371.5,1578.5 v1(1380,1570)
PTO-IN-1: J1.8 J17.7 | length 807.9
  Bottom Layer w8: J17.7@200,175 124.13,250.87 124.13,844.13 J1.8@200,920
PTO-IN-2: J1.18 J17.6 | length 380.1
  Bottom Layer w8: J1.18@200,420 140,360 140,260 180,220 217.55,220 218.2,219.35 218.37,219.35 218.6,219.13 255.87,219.13 J17.6@300,175
PTO-IN-3: J1.20 J17.5 | length 295.2
  Bottom Layer w8: J1.20@200,320 200,260 224.77,235.23 224.95,235.23 225.18,235 340,235 J17.5@400,175
PTO-OUT-1: J2.10 J2.12 J2.15 J11.2 J17.4 | length 2722.8
  Top Layer w8: J17.4@500,175 555,120 732.55,120 784.3,68.25 1723.25,68.25 1790,135 1790,160 ; v1(1735,280) 1790,225 1790,201.47 ; 1790,181.28 1790,201.47 ; 1790.37,180.9 1790,180.53 1790,160 ; 1790.37,201.1 1790,201.47 ; v1(1815,160) 1790,160
  Power Layer w8: v1(1735,280) 1735,321 1880,466 1951.02,466 J2.15@2000,514.98 ; J2.12@1900,714.98 J2.10@1900,814.98
  Bottom Layer w8: v1(1735,280) 1777.53,280 1777.9,279.63 1798.1,279.63 1798.47,280 1810,280 1823.25,293.25 1823.25,604.25 1900,681 J2.12@1900,714.98 ; v1(1815,160) 1854,160 1890,124 J11.2@1890,80
PTO-OUT-2: J2.14 J12.2 J17.3 | length 1981.7
  Power Layer w8: J17.3@600,175 715,60 1760,60 1790,90 1790,165 v1(1760,195) 1827,195 1842,210 J12.2@1890,210
  Bottom Layer w8: v1(1760,195) 1839.13,274.13 1839.13,554.11 J2.14@1900,614.98
PTO-OUT-3: J2.16 J17.2 | length 1542.2
  Top Layer w8: J17.2@700,175 790.87,84.13 1684.13,84.13 1754.5,154.5 v1@1764.5,154.5
  Bottom Layer w8: v1(1760,160) 1855,255 1855,475 J2.16@1894.98,514.98
PWREN1: J1.6 U9.3 | length 1323.5
  Top Layer w8: J1.6@200,1020 250,1070 250,1131.69 207.2,1174.49 145.51,1174.49 70.87,1249.13 70.87,1517.87 123,1570 490,1570 533.4,1613.4 U9.3@533.4,1805.87
PWREN2: J1.4 J2.20 U15.3 | length 6551.6
  Top Layer w8: J1.4@200,1120 177.55,1120 55,1242.55 55,2125 150,2220 151,2219 152,2220 v1(1302,2220) ; U15.3@1741.4,1805.87 1747.27,1800 v1(1780,1800)
  Power Layer w8: J1.4@200,1120 249,1071 249,794 225,770 175,770 140,735 140,110 160,90 662.55,90 708.42,44.13 1766.58,44.13 1846.8,124.35 2023.48,124.35 2045,145.87 2045,340 2025,360 1945.02,360 J2.20@1900,314.98
  Bottom Layer w8: v1(1302,2220) 1302,2138.02 1580.02,1860 1720,1860 v1(1780,1800)
SinCos-A: C7.1 J1.13 R6.2 | length 1473
  Top Layer w8: v1@965,1270 965,1322 992,1349 1104,1349 v1(1168,1285) 1165,1285 1160,1280 R6.2@1123.62,1280
  Bottom Layer w8: J1.13@300,620 344.13,664.13 344.13,921.58 697.55,1275 v1(965,1275) ; C7.1@1124.78,1276.49 1156.49,1276.49 1165,1285 v1(1168,1285)
SinCos-B: C17.1 J1.17 R15.2 | length 1578.2
  Bottom Layer w8: J1.17@300,420 360,480 360,915 693.78,1248.78 996.22,1248.78 1062.45,1315 1185.5,1315 ; R15.2@1186.38,1345 1185.5,1344.12 1185.5,1315 ; C17.1@1211.5,1292 C17.1@1210,1290.5 1185.5,1315
SPI-1-SIMO: J2.11 R36.1 | length 2395.6
  Top Layer w8: J2.11@2000,714.98 J2.11@2002.98,712
  Bottom Layer w8: R36.1@937.01,1810 970,1777.01 1036.54,1777.01 1088.25,1725.3 1088.25,1422.48 1116.85,1393.88 1633.78,1393.88 1820.77,1580.87 1996.58,1580.87 2045,1532.45 2045,759.98 J2.11@2000,714.98
SPI-1-SOMI: J2.13 R41.2 U7.4 | length 2728.4
  Top Layer w8: v1(895,1950) 911.5,1966.5 U7.4@948.36,1966.5
  Bottom Layer w8: v1(895,1950) 896.5,1948.5 R41.2@938.5,1948.5 940,1947.01 940,1890 989.43,1840.57 1024.6,1840.57 1065.75,1799.43 1065.75,1799.33 1089.33,1775.75 1089.43,1775.75 1104.13,1761.05 1104.13,1429.05 1123.42,1409.75 1627.2,1409.75 1814.2,1596.75 2003.15,1596.75 2060.87,1539.02 2060.87,675.86 J2.13@2000,614.98
SPI-2-SIMO: J2.7 J10.4 R51.1 | length 3117.7
  Top Layer w8: v1@1178.33,2015 1078,1914.67 1078,1584.55 1203.42,1459.13 1461.58,1459.13 1563.45,1561 1916.9,1561 2098.13,1379.77 2098.13,1013.11 J2.7@2000,914.98
  Power Layer w8: J2.7@2000,914.98 2097.37,817.61 2097.37,497.37 2065,465 2065,125 J10.4@2110,80
  Bottom Layer w8: R51.1@1178.5,1970 v1@1178.5,2013.5
  other v1: 1180,2015
SPI-2-SOMI: J2.5 J10.3 R57.2 U10.4 | length 2496.9
  Top Layer w8: U10.4@1232.72,1815 1298,1815 v1(1300,1813) ; v1(1586,1533) 1922.45,1533 2082.25,1373.2 2082.25,1089.68 2007.56,1014.98 J2.5@2000,1014.98
  Power Layer w8: J2.5@2000,1014.98 2113.25,901.74 2113.25,490.8 2155,449.05 2155,220 2110,175 J10.3@2110,193
  Bottom Layer w8: R57.2@1230,1821.5 1273.5,1821.5 1280,1815 1298,1815 v1(1300,1813) 1397,1813 1586,1624 v1(1586,1533)
"SPISTEA / SPISTEB": J2.3 R74.2 | length 207.2
  Bottom Layer w8: R74.2@1815,1168.5 1946.48,1168.5 J2.3@2000,1114.98
SPISTEC: J2.17 R73.2 | length 160.6
  Top Layer w8: J2.17@2000,414.98 2022.02,437 v1(2095,437)
  Bottom Layer w8: J2.17@2000,400 J2.17@2000,414.98 ; v1(2095,437) R73.2@2095,478.5
pads on no net: J1.2 J1.5 J1.7 J1.9 J1.10 J1.11 J1.12 J1.15 J1.16 J2.9 J2.18 J7.3 J7.5 J8.3 J8.5 U9.4 U9.5 U13.5 U14.4 U15.4 U15.5

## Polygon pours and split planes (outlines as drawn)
15V on Power Layer "POWER_LAYER_15V_P010" (solid, remove dead copper, pour order 10): 359.65,180 525,50 640,50 1205,50 1205,275 795,525 795,910 359.65,910
5V on Power Layer "POWER_LAYER_5V_P012" (solid, remove dead copper, pour order 12): 1210,50 1700,50 1825.89,175.89 1825.89,1186.38 1190,1190 863.39,1138.39 615,1126 615,1386.77 360,1415 360,1242.99 360,920.67 675.88,618.82 1210,285
3V3 on Power Layer "POWER_LAYER_3V3_P006" (solid, remove dead copper, pour order 6): 824.88,1940 628,1620 628,1540 628,1397 628,1137 877.5,1147.5 1190,1190 1819.91,1187.16 1819.91,1720 1500,1720 1500,1940
5V on Power Layer "POWER_LAYER_5V_P018" (solid, remove dead copper, pour order 18): 380,1360 80,1360 80,1520 550,2170 1700,2170 1820,2100 1820,1740 1500,1745 615,1336 615,1256.9
GND on Top Layer "TOP_LAYER_GND_P023" (solid, remove dead copper, pour order 23): 0,0 2200,0 2200,2300 0,2300
GND on Bottom Layer "BOTTOM_LAYER_GND_P025" (solid, remove dead copper, pour order 25): 0,2300 2200,2300 2200,0 0,0
GND on Ground Plane (split plane): 2179.9,1670 1865,1670 1600,1405 700,1405 700,1325 1645,1325 1910,1590 2179.9,1590 2179.9,20.1 20.1,20.1 20.1,2279.9 2179.9,2279.9

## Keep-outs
Keep-Out Layer:
  the board outline again, w10
  text ".Layer_Name" at 577,-858.49 h60

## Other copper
Top Layer:
  region net 5V: 834.1,1094.14 899.1,1094.14 899.1,1134.14 834.1,1134.14
  region net 5V: 724.1,1149.14 789.1,1149.14 789.1,975 724.1,975
  region net 3V3: 724.1,1159.14 789.1,1159.14 789.1,1339.14 724.1,1339.14
  region net GND: 799.1,974.14 799.1,1194.14 799.1,1339.14 899.1,1339.14 899.1,1254.14 824.1,1254.14 824.1,1194.14 869.1,1194.14 869.1,1254.14 899.1,1254.14 899.1,1154.14 944.1,1154.14 944.1,1144.14 824.1,1144.14 824.1,1084.14 909.1,1084.14 909.1,1144.14 944.1,1144.14 944.1,974.14
  region net 5V: 1460,865 1460,1025 1490,1025 1490,865
  region net 1V65: 1415,841 1415,910 1350,910 1350,841
  region net AbsEnc2-5V: 1680,1880 1680,1950 1610,1950 1610,1880
  region net 5V: 1680,1830 1610,1830 1610,1770 1680,1770
  region net 5V: 470,1840 390,1840 390,1730 470,1730
  region net AbsEnc1-5V: 470,1960 470,1870 390,1870 390,1960
  text ".Layer_Name" at 577,-858.49 h60
Power Layer:
  region net 1V65: 1104.71,880 1104.71,820 1680,820 1680,880
Bottom Layer:
  region net NetC56_2: 670,870 807,870 820,894 820,972 745,972 745,942 670,942
  region net 15V: 798,800 798,862 742,862 689.44,840 689.44,800
  region net 5V: 1700,1690 1700,1810 1590,1810 1590,1690
  region net AbsEnc2-5V: 1700,2030 1700,1880 1590,1880 1590,2030
  region net AbsEnc1-5V: 490,2040 390,2040 390,1870 490,1870
  region net 5V: 390,1800 490,1800 490,1670 390,1670
  text ".Layer_Name" at 577,-858.49 h60
Ground Plane (plane layer: these items are gaps in the copper):
  pour cut-out: 1600,1405 1865,1670 2220,1670 2220,1590 1910,1590 1645,1325 700,1325 700,1405

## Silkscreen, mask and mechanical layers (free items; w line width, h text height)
Top Overlay:
  region: 2190,1212.75 2190,1258.25 2087.5,1258.25 2041.75,1212.5 2086.25,1167.5 2190,1167.5 2190,1212.75 2185,1212.75 2185,1175 2089.25,1175 2052.25,1212.25 2052.25,1213.25 2089.25,1250.25 2185,1250.25 2185,1212.75
  region: 20,1221 20,1176.5 115.93,1176.5 145,1221 115.93,1260 20,1260 20,1221 40,1221 40,1240 115.93,1240 115.93,1200 40,1200 40,1221
  lines w6: 2040,95 2040,635 ; 2040,595.48 2040,900.5 2050.5,911 ; 2040,615 2040,679.98 ; 2040,840 2055,855 ; 2162,89 2184,111 2184,778 2184,807 ; 2162,188 2184,210 ; 2162,287 2184,309 ; 2162,385 2184,407
  text ".Layer_Name" at -5,2940 h30
  text "Master" at 944,2205 h20
  text "Slave" at 1149,2205 h20
  text "Abs-Enc 1" at 944,2003 h20
  text "Abs-Enc 1" at 65,1540 h30
  text "Abs-Enc 2" at 1880,1530.5 h30
  text "5V" at 635,1400 h30 r270
  text "LaunchPad" at 60,1349 h20
  text "External" at 280,1349 h20
  text "GND" at 635,1285 h30 r270
  text "J1" at 175,1269 h25
  text "J3" at 273,1269 h25
  text "J4" at 1873,1265 h25
  text "J2" at 1971,1265 h25
  text "3V3" at 40,1205 h50
  text "GND" at 2080,1200 h50
  text "TIDM-1008 Rev-E2" at 46,1084 h60 r270
  text "15V" at 635,1045 h30 r270
  text "GND" at 635,915 h30 r270
  text "CLK" at 2171,752 h20 r90
  text "TxEn" at 2171,642 h20 r90
  text "SOMI" at 2171,547 h20 r90
  text "Abs-Enc 2" at 2121,448 h20 r90
  text "SIMO" at 2171,447 h20 r90
  text "Exc" at 905,210 h30
  text "GND" at 905,110 h30
  text "IN-1" at 165,80 h20
  text "IN-2" at 265,80 h20
  text "IN-3" at 365,80 h20
  text "OUT-1" at 455,80 h20
  text "OUT-2" at 555,80 h20
  text "OUT-3" at 665,80 h20
  text "GND" at 775,80 h20
  text "Resolver" at 881,53.38 h30
  text "PTO" at 460,20 h30
  text "SinCos-Enc" at 825,9 h30
Bottom Overlay:
  text ".Layer_Name" at 577,-858.49 h30
Top Paste:
  text ".Layer_Name" at 577,-858.49 h60
Bottom Paste:
  text ".Layer_Name" at 577,-858.49 h60
Top Solder:
  text ".Layer_Name" at 577,-858.49 h60
  text ".Layer_Name" at 577,-858.49 h60
Bottom Solder:
  text ".Layer_Name" at 577,-858.49 h60
Drill Guide:
  text ".Layer_Name" at 577,-858.49 h60
M1 Board Outline:
  the board outline again, w10
  text ".Layer_Name" at 577,-858.49 h60
M2 Board Dimensions:
  rectangle: 0,-275 125,-150
  rectangle: 125,-400 500,-275
  lines w7: 0,-275 1000,-275 ; 125,-400 125,-150 ; 250,-400 250,-150 ; 500,-400 500,-150 ; 750,-400 750,-150 ; 0,-400 1000,-400 1000,-150 0,-150 0,-400
  text ".Layer_Name" at 577,-858.49 h60
M3 3D STEP Top:
  text ".Layer_Name" at 577,-858.49 h60
M4 3D STEP Bottom:
  text ".Layer_Name" at 577,-858.49 h60
M5 Assembly Top:
  lines w10: -292,-930.17 6308,-930.17 ; -292,-726.83 6310,-726.83 ; -292,-523.5 -292,-1133.5 3713,-1133.5 6310,-1133.5 6310,-523.5 -291.5,-523.5 -291.5,-1133.5 1284,-1133.5 ; 2173,-1133.5 2173,-523.5 ; 3440,-726.83 3440,-523.5 ; 4280,-726.83 4280,-523.5 ; 4902,-1140 4902,-937.17
  text "COMPONENTS MARKED 'DNP' SHOULD NOT BE POPULATED." at 1153.5,-318.5 h60
  text "ASSEMBLY VARIANT:" at 1153,-434 h60
  text ".VariantName" at 2189,-434 h60
  text "PCB VIEWED FROM TOP SIDE" at -228.5,-655.67 h60
  text "BOARD #:" at 2248,-655.67 h60
  text ".PRJ_Number" at 2793.5,-655.67 h60
  text "REV:" at 3638,-655.67 h60
  text ".PCB_Rev" at 3929.5,-655.67 h60
  text "SVN REV:" at 4476,-655.67 h60
  text ".VersionControl_RevNumber" at 4982,-655.67 h60
  text "TID #:" at 2248,-859 h60
  text ".TID" at 2793.5,-859 h60
  text "PLOT NAME =" at -228.5,-1064.34 h60
  text ".plot_File_Name" at 577,-1064.34 h60
  text "GENERATED    :" at 2250,-1064.34 h60
  text ".Print_Date" at 3119.5,-1064.34 h60
  text ".Print_Time" at 3848.5,-1064.34 h60
  text "TEXAS INSTRUMENTS" at 5113,-1064.34 h60
M6 Assembly Bottom:
  lines w10: -292.5,-727.33 6309.5,-727.33 ; -290.5,-930.67 6309.5,-930.67 ; 1115.5,-1140.5 1115.5,-937.67 ; 1737.5,-727.33 1737.5,-524 ; 2577.5,-727.33 2577.5,-524 ; 3844.5,-1134 3844.5,-524 ; 4733.5,-1134 6309,-1134 6309,-524 -292.5,-524 -292.5,-1134 2304.5,-1134 6309.5,-1134 6309.5,-524
  text "COMPONENTS MARKED 'DNP' SHOULD NOT BE POPULATED." at 6102,-318 h60
  text ".VariantName" at 5058,-434 h60
  text "ASSEMBLY VARIANT:" at 6097,-434 h60
  text ".VersionControl_RevNumber" at 1035.5,-656.17 h60
  text "SVN REV:" at 1541.5,-656.17 h60
  text ".PCB_Rev" at 2088,-656.17 h60
  text "REV:" at 2379.5,-656.17 h60
  text ".PRJ_Number" at 3224,-656.17 h60
  text "BOARD #:" at 3769.5,-656.17 h60
  text "PCB VIEWED FROM BOTTOM SIDE" at 6246,-656.17 h60
  text ".TID" at 3224,-859.5 h60
  text "TID #:" at 3769.5,-859.5 h60
  text "TEXAS INSTRUMENTS" at 904.5,-1064.84 h60
  text ".Print_Time" at 2169,-1064.84 h60
  text ".Print_Date" at 2898,-1064.84 h60
  text "GENERATED    :" at 3767.5,-1064.84 h60
  text ".plot_File_Name" at 5440.5,-1064.84 h60
  text "PLOT NAME =" at 6246,-1064.84 h60
M9 Title Sheet:
  drawing of 57 lines, arcs and shapes, not listed
  text "1" at 739.84,8036.5 h70
  text "2" at 3235.5,8036.5 h70
  text "3" at 5724.84,8036.5 h70
  text "4" at 8231.51,8036.5 h70
  text "5" at 10730.5,8036.5 h70
  text "6" at 13235.5,8036.5 h70
  text "A" at -416.5,6893.5 h70
  text "A" at 14383.5,6893.5 h70
  text "B" at -416.5,4513.5 h70
  text "B" at 14383.5,4513.5 h70
  text "C" at -416.5,2138.5 h70
  text "C" at 14383.5,2138.5 h70
  text "PROJECT TITLE:" at 11343.5,277.5 h45
  text ".PRJ_Title" at 11393.5,144.17 h70
  text "DESIGNED FOR:" at 11343.5,-23.5 h45
  text ".PRJ_Customer" at 11393.5,-163.5 h70
  text "D" at -416.5,-231.5 h70
  text "D" at 14383.5,-231.5 h70
  text "FILE NAME:" at 11343.5,-323.5 h45
  text ".PCB_File_Name_No_Path" at 11393.5,-443.5 h70
  text "Texas Instruments (TI) and/or its licensors do not warrant the accuracy or completeness of this specification" at 6374,-605.34 h45
  text "ENGINEER:" at 11343.5,-613.5 h45
  text "LAYOUT BY:" at 12848.5,-613.5 h45
  text "or any information contained therein. TI and/or its licensors do not warrant that this design will meet" at 6329.01,-718 h45
  text ".PRJ_Engineer" at 11393.5,-768.49 h70
  text ".PCB_Layout" at 12899,-768.49 h70
  text "the specifications, will be suitable for your application or fit for any particular purpose, or will operate in" at 6329.01,-830.67 h45
  text ".Layer_Name" at 577,-858.49 h60
  text "ALTIUM DESIGNER VERSION:" at 12848.5,-923.5 h45
  text "an implementation. TI and/or its licensors do not warrant that the design is production worthy. You should" at 6329.01,-943.33 h45
  text "completely validate and test your design implementation to confirm the system functionality for your application." at 6374,-1056 h45
  text ".print_Scale" at 11393.5,-1056.83 h70
  text ".Application_BuildNumber" at 12899,-1056.83 h70
  text "1" at 739.84,-1263.5 h70
  text "2" at 3235.5,-1263.5 h70
  text "3" at 5724.84,-1263.5 h70
  text "4" at 8231.51,-1263.5 h70
  text "5" at 10730.5,-1263.5 h70
  text "6" at 13235.5,-1263.5 h70
M10 Fab Notes:
  drawing of 173 lines, arcs and shapes, not listed
  text "DESIGN INFORMATION" at 12378.02,6201 h60
  text "MIN. TRACK WIDTH:" at 11733.46,6021 h60
  text "8" at 12829.7,6021 h60
  text "MIL" at 12984.46,6021 h60
  text "MIN. CLEARANCE:" at 11733.46,5889 h60
  text "0.2" at 12769.7,5889 h60
  text "mm" at 12984.46,5889 h60
  text "MIN. VIA PAD SIZE:" at 11733.46,5757 h60
  text "24" at 12799.71,5757 h60
  text "MIL" at 12984.46,5757 h60
  text "0.05mm (2MIL)" at 12428.46,5615.29 h60
  text "MINIMUM ANNULAR RING" at 11404.23,5611 h60
  text "EXTERNAL" at 13136.46,5611 h60
  text "PER" at 11604.23,5493 h60
  text "IPC-D-275 CLASS 2 LEVEL C" at 11824.23,5493 h60
  text "MIL, HOLES" at 13312.46,5380.71 h60
  text "+/-" at 12920,5380 h60
  text "+/-" at 13774,5380 h60
  text "REGISTRATION TOLERANCES:" at 11404.23,5375 h60
  text "METAL" at 12604,5375 h60
  text "5" at 13180.2,5375 h60
  text "5" at 14013.2,5375 h60
  text "MIL" at 14129.46,5375 h60
  text "+/-" at 13774,5262 h60
  text "HOLE SIZE TOLERANCE (UNLESS OTHERWISE SPECIFIED):" at 11404.23,5257 h60
  text "4" at 14013.2,5257 h60
  text "MIL" at 14129.46,5257 h60
  text "MATERIAL:" at 11329.46,5047.54 h60
  text "FR-4 High Tg" at 12315.9,4907.21 h60
  text "FR-408" at 11750.46,4898.64 h60
  text "OTHER" at 13238.46,4898.64 h60
  text "X" at 12161,4895 h60
  text "62 MIL (1.6mm) +/-10%" at 12070.56,4735.92 h60
  text "THICKNESS:" at 11404.23,4731.64 h60
  text "X" at 11942.4,4731.64 h60
  text "OTHER" at 13355.46,4731.64 h60
  text "TOLERANCE:" at 11404.23,4573.64 h60
  text "X" at 12243.53,4573.64 h60
  text "ANSI IPC-6012 TYPE 3 CLASS 2" at 12430.48,4573.64 h60
  text "OTHER +/-" at 12430.46,4417.64 h60
  text "BOW & TWIST:" at 11404.23,4260.64 h60
  text "X" at 12243.53,4260.64 h60
  text "ANSI IPC-6012 TYPE 3 CLASS 2" at 12430.48,4260.64 h60
  text "OTHER +/-" at 12430.46,4102.13 h60
  text "DRILLING:" at 11329.46,3963.64 h60
  text "REFERENCE:" at 11404.23,3846.64 h60
  text "X" at 12052.46,3846.64 h60
  text "AS SHOWN" at 12239.46,3846.64 h60
  text "X" at 12953.46,3846.64 h60
  text "NC_DRILL FILES" at 13090.46,3846.64 h60
  text "PTH COPPER THICKNESS:" at 11404.23,3688.64 h60
  text "X" at 12534.46,3688.64 h60
  text "20-30 um" at 12671.46,3688.64 h60
  text "OTHER" at 13388.46,3688.64 h60
  text "BOARD FINISH:" at 11329.46,3529.64 h60
  text "SILKSCREEN:" at 11484.68,3411.64 h60
  text "X" at 12433.46,3411.64 h60
  text "TOP" at 12559.46,3411.64 h60
  text "X" at 12943.46,3411.64 h60
  text "BOTTOM" at 13070.46,3411.64 h60
  text "SILKSCREEN COLOR:" at 11484.68,3244.64 h60
  text "X" at 12432.42,3244.64 h60
  text "WHITE" at 12559.46,3244.64 h60
  text "OTHER" at 13070.46,3244.64 h60
  text "X" at 12563.42,3085.44 h60
  text "GREEN" at 12690.46,3085.44 h60
  text "OTHER" at 13308.46,3085.44 h60
  text "SOLDER RESIST COLOR:" at 11484.68,3074.64 h60
  text "X" at 12563.42,2915.44 h60
  text "MATTE" at 12690.46,2915.44 h60
  text "SEMI-GLOSS" at 13308,2914.8 h60
  text "IMMERSION GOLD (ENIG)" at 12390.46,2726.92 h60
  text "ENEPIG" at 13728,2723.64 h60
  text "SURFACE FINISH:" at 11329.46,2722.64 h60
  text "X" at 12203.51,2722.64 h60
  text "IMM. TIN/SILVER OR EQUIV" at 11659,2565.64 h60
  text "OTHER" at 13090.46,2565.64 h60
  text "ARRAY/PANEL:" at 11329.46,2386.64 h60
  text "CUT AND TRIM PER M1 BOARD OUTLINE" at 12390.46,2382.35 h60
  text "N.C. ROUTE" at 12390.46,2230.64 h60
  text "X" at 13069.46,2230.64 h60
  text "V. SCORE" at 13256.46,2230.64 h60
  text "CERTIFICATION:" at 11329.46,2093.64 h60
  text "MATERIALS AND WORKMANSHIP FOR ALL PCBS" at 12054.46,2093.64 h60
  text "TO MEET OR EXCEED THE REQUIREMENTS OF:" at 12054.46,1995.64 h60
  text "X" at 11680.96,1859.13 h60
  text "ANSI IPC-A-600F CLASS ->" at 11819.96,1859.13 h60
  text "X" at 13459.02,1859.13 h60
  text "2" at 13577.96,1859.14 h60
  text "1" at 13262.96,1857.64 h60
  text "3" at 13931.96,1857.64 h60
  text "X" at 12495.02,1699.64 h60
  text "RoHS" at 12631.96,1699.64 h60
  text "OTHER" at 13276.36,1699.64 h60
  text "PER ORDER" at 13673.42,1699.64 h60
  text "ALL BOARDS MUST MEET OR EXCEED UL94-V0 REQUIREMENTS." at 11357,1534 h60
  text "PCB MUST BEAR THE UL94V-0 UL REGISTERED MATERIAL ID NUMBER" at 11357,1414 h60
  text "ADDITIONAL REQUIREMENTS:" at 11329.46,1240.64 h60
  text "MICROSECTION:" at 11404.23,1125.64 h60
  text "YES" at 12309.96,1125.64 h60
  text "REQUIRED" at 13171.46,969.49 h60
  text "BARE BOARD ELEC. TEST:" at 11404.23,966.64 h60
  text "NONE" at 12709.96,966.64 h60
  text "X" at 13044.46,966.64 h60
  text "PER ORDER" at 13763.46,966.64 h60
  text ".Layer_Name" at 577,-858.49 h60
M11 Gerber Information:
  lines w10: -292,-930.17 6308,-930.17 ; -292,-726.83 6310,-726.83 ; -292,-523.5 -292,-1133.5 3713,-1133.5 6310,-1133.5 6310,-523.5 -291.5,-523.5 -291.5,-1133.5 1284,-1133.5 ; 2173,-1133.5 2173,-523.5 ; 3440,-726.83 3440,-523.5 ; 4280,-726.83 4280,-523.5 ; 4902,-1140 4902,-937.17
  text "ALL ARTWORK VIEWED FROM TOP SIDE" at -228.5,-655.67 h60
  text "BOARD #:" at 2248,-655.67 h60
  text ".PRJ_Number" at 2793.5,-655.67 h60
  text "REV:" at 3638,-655.67 h60
  text ".PCB_Rev" at 3929.5,-655.67 h60
  text "SVN REV:" at 4476,-655.67 h60
  text ".VersionControl_RevNumber" at 4982,-655.67 h60
  text "LAYER NAME =" at -228.5,-858.49 h60
  text "TID #:" at 2248,-859 h60
  text ".TID" at 2793.5,-859 h60
  text "PLOT NAME =" at -228.5,-1064.34 h60
  text ".plot_File_Name" at 577,-1064.34 h60
  text "GENERATED    :" at 2250,-1064.34 h60
  text ".Print_Date" at 3119.5,-1064.34 h60
  text ".Print_Time" at 3848.5,-1064.34 h60
  text "TEXAS INSTRUMENTS" at 5113,-1064.34 h60
M12 Stackup:
  drawing of 191 lines, arcs and shapes, not listed
  text "Layer" at 9790.34,7830 h60
  text "Name" at 10200.26,7830 h60
  text "Material" at 11130,7830 h60
  text "Thickness" at 11989.77,7830 h60
  text "Constant" at 12639.6,7830 h60
  text "Board Layer Stack" at 13209.46,7830 h60
  text "1" at 9790.34,7710 h60
  text "Top Overlay" at 10200.26,7710 h60
  text "2" at 9790.34,7590 h60
  text "Top Solder" at 10200.26,7590 h60
  text "Solder Resist" at 11130,7590 h60
  text "0.40mil" at 11989.77,7590 h60
  text "3.5" at 12639.6,7590 h60
  text "3" at 9790.34,7470 h60
  text "Top Layer" at 10200.26,7470 h60
  text "Copper" at 11130,7470 h60
  text "1.40mil" at 11989.77,7470 h60
  text "4" at 9790.34,7350 h60
  text "Dielectric1" at 10200.26,7350 h60
  text "FR-4" at 11130,7350 h60
  text "59.20mil" at 11989.77,7350 h60
  text "4.8" at 12639.6,7350 h60
  text "5" at 9790.34,7230 h60
  text "Bottom Layer" at 10200.26,7230 h60
  text "Copper" at 11130,7230 h60
  text "1.40mil" at 11989.77,7230 h60
  text "6" at 9790.34,7110 h60
  text "Bottom Solder" at 10200.26,7110 h60
  text "Solder Resist" at 11130,7110 h60
  text "0.40mil" at 11989.77,7110 h60
  text "3.5" at 12639.6,7110 h60
  text "7" at 9790.34,6990 h60
  text "Bottom Overlay" at 10200.26,6990 h60
  text ".Layer_Name" at 577,-858.49 h60
M13 Component Bodies Top:
  text ".Layer_Name" at 577,-858.49 h60
M14 Component Bodies Bottom:
  text ".Layer_Name" at 577,-858.49 h60
M15 Courtyards Top:
  text ".Layer_Name" at 577,-858.49 h60
M16 Courtyards Bottom:
  text ".Layer_Name" at 577,-858.49 h60
Drill Drawing:
  circle w10: c5318.92,3376.61 r11.04
  lines w10: 5307.89,3166.94 5318.92,3172.46 5329.96,3166.94 5324.44,3177.97 5329.96,3189.01 5318.92,3183.49 5307.89,3189.01 5313.4,3177.97 5307.89,3166.94 ; 5307.89,3222.12 5313.4,3222.12 5313.4,3216.6 5324.44,3216.6 5324.44,3222.12 5329.96,3222.12 5329.96,3233.15 5324.44,3233.15 5324.44,3238.67 5313.4,3238.67 5313.4,3233.15 5307.89,3233.15 5307.89,3222.12 ; 5307.89,3288.33 5329.96,3288.33 5318.92,3266.26 5307.89,3288.33 ; 5307.89,3315.92 5307.89,3321.44 5313.4,3326.95 5307.89,3332.47 5307.89,3337.99 5313.4,3337.99 5318.92,3332.47 5324.44,3337.99 5329.96,3337.99 5329.96,3332.47 5324.44,3326.95 5329.96,3321.44 5329.96,3315.92 5324.44,3315.92 5318.92,3321.44 5313.4,3315.92 5307.89,3315.92
  lines w12: 5286,3152.04 6841.61,3152.04 ; 5286,3400.34 6841.61,3400.34 ; 5443.74,3102.38 5443.74,3450 ; 5602.29,3102.38 5602.29,3450 ; 5913.11,3102.38 5913.11,3450 ; 6035.21,3102.38 6035.21,3450 ; 6215.33,3102.38 6215.33,3450 ; 6569.56,3102.38 6569.56,3450 ; 5286,3102.38 6841.61,3102.38 6841.61,3450 5286,3450 5286,3102.38
  text "Symbol" at 5315.8,3415.24 h36
  text "Quantity" at 5458.64,3415.24 h36
  text "Finished Hole Size" at 5617.19,3415.24 h36
  text "Plated" at 5928.01,3415.24 h36
  text "Hole Type" at 6050.1,3415.24 h36
  text "Drill Layer Pair" at 6230.23,3415.24 h36
  text "Hole Tolerance" at 6584.46,3415.24 h36
  text "167" at 5458.64,3365.58 h30
  text "15.00mil (0.381mm)" at 5617.19,3365.58 h30
  text "PTH" at 5928.01,3365.58 h30
  text "Round" at 6050.1,3365.58 h30
  text "Top Layer - Bottom Layer" at 6230.23,3365.58 h30
  text "4" at 5458.64,3315.92 h30
  text "35.43mil (0.900mm)" at 5617.19,3315.92 h30
  text "PTH" at 5928.01,3315.92 h30
  text "Round" at 6050.1,3315.92 h30
  text "Top Layer - Bottom Layer" at 6230.23,3315.92 h30
  text "25" at 5458.64,3266.26 h30
  text "40.00mil (1.016mm)" at 5617.19,3266.26 h30
  text "PTH" at 5928.01,3266.26 h30
  text "Round" at 6050.1,3266.26 h30
  text "Top Layer - Bottom Layer" at 6230.23,3266.26 h30
  text "40" at 5458.64,3216.6 h30
  text "40.95mil (1.040mm)" at 5617.19,3216.6 h30
  text "PTH" at 5928.01,3216.6 h30
  text "Round" at 6050.1,3216.6 h30
  text "Top Layer - Bottom Layer" at 6230.23,3216.6 h30
  text "24" at 5458.64,3166.94 h30
  text "44.88mil (1.140mm)" at 5617.19,3166.94 h30
  text "PTH" at 5928.01,3166.94 h30
  text "Round" at 6050.1,3166.94 h30
  text "Top Layer - Bottom Layer" at 6230.23,3166.94 h30
  text "260 Total" at 5458.64,3117.28 h30
  text ".Layer_Name" at 577,-858.49 h60
M17 Embedded Cavity:
  text ".Layer_Name" at 577,-858.49 h60
M18 Embedded Assembly:
  text ".Layer_Name" at -5,2710 h60
M19 Embedded Keepout:
  text ".Layer_Name" at 577,-858.49 h60

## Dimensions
0,-400 to 1000,-400 on M2 Board Dimensions
0,0 to 0,2300 on M2 Board Dimensions
0,0 to 2200,0 on M2 Board Dimensions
